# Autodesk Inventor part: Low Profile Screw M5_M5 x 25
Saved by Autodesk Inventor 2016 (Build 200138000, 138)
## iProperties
Created: 2015-11
Part Number: Low Profile Screw M5_M5 x 25
Material: Generic
Document SubType Name: Modeling
Designer: John
Density: 1 g/cm^3
Appearance: Default
Author: John
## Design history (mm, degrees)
feature "SOLID1"
body "Solid1"
